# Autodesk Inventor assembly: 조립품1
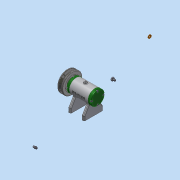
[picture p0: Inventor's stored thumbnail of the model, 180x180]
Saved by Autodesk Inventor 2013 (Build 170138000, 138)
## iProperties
Created: 2018-05
Part Number: 조립품1
Document SubType Name: Assembly
Designer: dgall
Author: dgall
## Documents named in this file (16)
- C:\Users\dgall\Desktop\480507V1031\조립품1.iam
- C:\Users\dgall\Desktop\480507V1031\V벨트풀리.ipt
- C:\Users\dgall\Desktop\480507V1031\너트 M8.ipt
- C:\Users\dgall\Desktop\480507V1031\니플 M6x0.75.ipt
- C:\Users\dgall\Desktop\480507V1031\뒤커버.ipt
- C:\Users\dgall\Desktop\480507V1031\베어링 6002.ipt
- C:\Users\dgall\Desktop\480507V1031\본체1.ipt
- C:\Users\dgall\Desktop\480507V1031\볼트 M4x12.ipt
- C:\Users\dgall\Desktop\480507V1031\볼트 M6x8.ipt
- C:\Users\dgall\Desktop\480507V1031\스프링와셔 8.ipt
- C:\Users\dgall\Desktop\480507V1031\앞커버.ipt
- C:\Users\dgall\Desktop\480507V1031\오일 실 15 25 7.ipt
- C:\Users\dgall\Desktop\480507V1031\와셔 6x11.5.ipt
- C:\Users\dgall\Desktop\480507V1031\와셔 8x17.ipt
- C:\Users\dgall\Desktop\480507V1031\축.ipt
- C:\Users\dgall\Desktop\480507V1031\키 3x3x12.ipt
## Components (1 placed, 1 different names)
1. V벨트풀리:1
